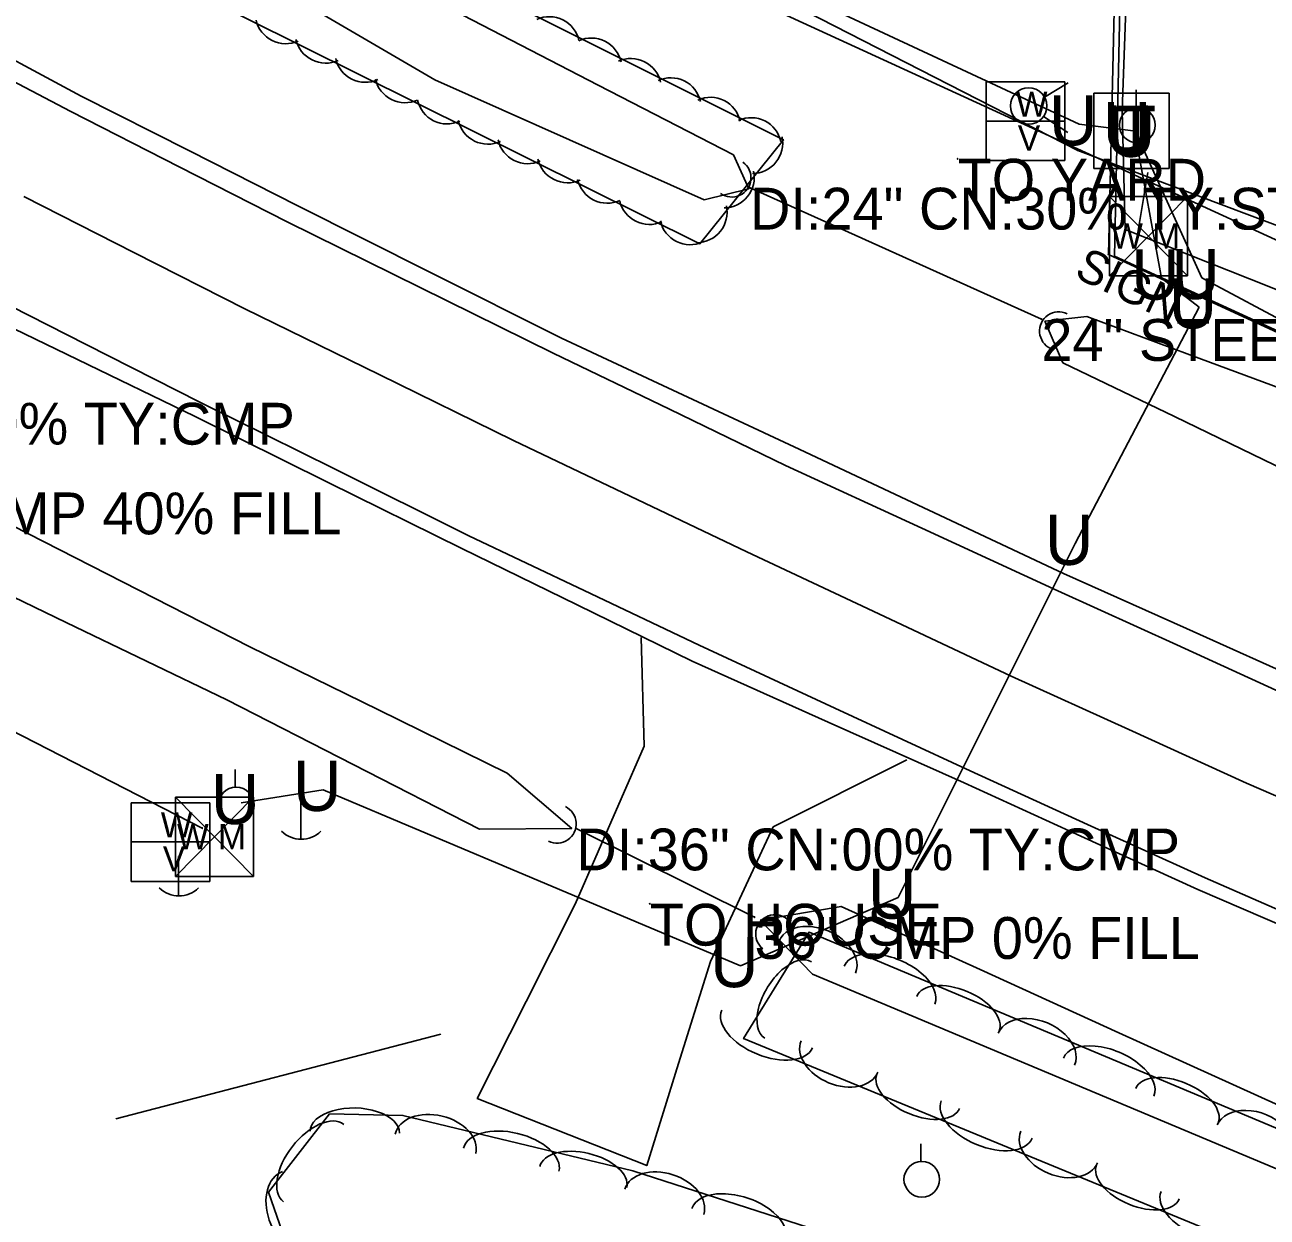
# Model space of a CAD drawing. Extents: x 1441650 to 1491889, y 345904 to 358319.
# Drawn here: x 1445494.4 to 1445643, y 354585.4 to 354728 of the extents above; entities that cross this region are included whole.
import ezdxf

# ---------------------------------------------------------------- set-up
doc = ezdxf.new("R2010")
doc.units = 0
for name, color, linetype in [('Default', 7, 'Continuous'), ('S_CROSS_DRAIN', 7, 'Continuous'), ('S_CROSS_DRAIN_ANNOT', 7, 'Continuous'), ('S_DITCHLINE', 7, 'Continuous'), ('S_DRG_PT_SYM', 7, 'Continuous'), ('S_EDGE_PAVEMENT', 7, 'Continuous'), ('S_FENCE', 7, 'Continuous'), ('S_GAS_UTILITIES', 7, 'Continuous'), ('S_GRAVEL_ROAD', 7, 'Continuous'), ('S_MSC_PT_SYM', 7, 'Continuous'), ('S_PAVEMENT_CROWN', 7, 'Continuous'), ('S_SHOULDER', 7, 'Continuous'), ('S_SIGN_ANNOT', 7, 'Continuous'), ('S_SURVEY_TEXT_ANNOT', 7, 'Continuous'), ('S_TELEPHONE_UTILITIES', 7, 'Continuous'), ('S_TRAILS', 7, 'Continuous'), ('S_TREE', 7, 'Continuous'), ('S_UNDERGROUND_CABLE', 7, 'Continuous'), ('S_UTILITY_POLE', 7, 'Continuous'), ('S_UTL_PT_SYM', 7, 'Continuous'), ('S_WATER_UTILITIES', 7, 'Continuous')]:
    doc.layers.add(name, color=color, linetype=linetype)

msp = doc.modelspace()

# ---------------------------------------------------------------- linework, layer by layer
at = {"layer": 'S_CROSS_DRAIN'}
for p, q in [((1445581.12, 354708.5), (1445615.98, 354692.8)), ((1445560.34, 354631.87), (1445581.67, 354621.28))]:
    msp.add_line(p, q, dxfattribs=at)
for centre, start, end in [((1445578.94, 354709.69), 234.4858, 54.815), ((1445618.06, 354691.36), 64.431, 244.7602), ((1445558.03, 354632.42), 243.9904, 64.3196), ((1445584.1, 354619.27), 50.7104, 231.0396)]:
    msp.add_arc(centre, 2.3, start, end, dxfattribs=at)
at = {"layer": 'S_DITCHLINE'}
for points in [[(1445507.34, 354745.43), (1445514.42, 354744.42), (1445530.6, 354736.77), (1445546.78, 354729.13), (1445562.96, 354720.78), (1445579.14, 354712.42), (1445580.96, 354708.37), (1445575.63, 354707.06), (1445559.53, 354714.22), (1445543.42, 354721.39), (1445526.18, 354731.48), (1445508.94, 354741.57)], [(1445616.39, 354692.54), (1445618.56, 354687.58), (1445631.89, 354681.14), (1445645.22, 354674.69), (1445661.2, 354667.77), (1445677.18, 354660.84), (1445681.37, 354663.16), (1445677.91, 354667.65), (1445663.36, 354675.29), (1445648.8, 354682.93), (1445635.12, 354688.02), (1445621.43, 354693.11)], [(1445475.5, 354671.85), (1445483.37, 354672.92), (1445502.31, 354663.27), (1445521.26, 354653.62), (1445536.66, 354646.05), (1445552.07, 354638.49), (1445559.8, 354631.89), (1445548.74, 354631.79), (1445533.63, 354639.52), (1445518.52, 354647.25), (1445499.3, 354656.52), (1445480.07, 354665.8)]]:
    msp.add_lwpolyline(points, close=True, dxfattribs=at)
for points in [[(1445582.34, 354620.9), (1445592.01, 354622.56), (1445608.64, 354615.01), (1445625.26, 354607.46), (1445641.89, 354599.91), (1445658.52, 354592.36), (1445679.06, 354584.26), (1445699.61, 354576.16), (1445720.15, 354568.06), (1445740.7, 354559.96), (1445763.19, 354552.12), (1445785.68, 354544.28)], [(1445582.34, 354620.91), (1445588.59, 354614.45), (1445606.17, 354607.08), (1445623.76, 354599.71), (1445641.34, 354592.33), (1445658.93, 354584.96), (1445678.55, 354576.91), (1445698.18, 354568.86), (1445717.81, 354560.81), (1445737.43, 354552.76), (1445759.94, 354544.74), (1445782.44, 354536.73)]]:
    msp.add_lwpolyline(points, dxfattribs=at)
at = {"layer": 'S_DRG_PT_SYM'}
for points in [[(1445581.12, 354708.5), (1445581.12, 354708.55), (1445581.12, 354708.5), (1445581.07, 354708.5), (1445581.12, 354708.5), (1445581.12, 354708.45), (1445581.12, 354708.5), (1445581.17, 354708.5)], [(1445615.98, 354692.8), (1445615.98, 354692.85), (1445615.98, 354692.8), (1445615.93, 354692.8), (1445615.98, 354692.8), (1445615.98, 354692.75), (1445615.98, 354692.8), (1445616.03, 354692.8)], [(1445560.34, 354631.87), (1445560.34, 354631.92), (1445560.34, 354631.87), (1445560.29, 354631.87), (1445560.34, 354631.87), (1445560.34, 354631.82), (1445560.34, 354631.87), (1445560.39, 354631.87)], [(1445581.67, 354621.28), (1445581.67, 354621.33), (1445581.67, 354621.28), (1445581.62, 354621.28), (1445581.67, 354621.28), (1445581.67, 354621.23), (1445581.67, 354621.28), (1445581.72, 354621.28)]]:
    msp.add_lwpolyline(points, dxfattribs=at)
at = {"layer": 'S_EDGE_PAVEMENT'}
for points in [[(1445484.93, 354725.42), (1445499.88, 354717.6), (1445512.81, 354711.01), (1445525.74, 354704.41), (1445541.65, 354696.57), (1445557.56, 354688.73), (1445571.47, 354682.02), (1445585.38, 354675.3), (1445601.66, 354667.81), (1445617.95, 354660.31), (1445632.18, 354653.82), (1445646.4, 354647.34), (1445662.43, 354640.42), (1445678.45, 354633.5), (1445695.75, 354626.25), (1445713.05, 354619.01), (1445724.98, 354614.31), (1445736.91, 354609.62), (1445758.93, 354600.82), (1445773.25, 354595.45)], [(1445488.09, 354696.66), (1445501.69, 354689.76), (1445515.29, 354682.87), (1445531.39, 354674.88), (1445547.49, 354666.89), (1445561.27, 354660.34), (1445575.05, 354653.79), (1445591.25, 354646.28), (1445607.45, 354638.77), (1445621.51, 354632.37), (1445635.57, 354625.97), (1445651.53, 354619.01), (1445667.49, 354612.05), (1445685.63, 354604.56), (1445703.76, 354597.07), (1445715.54, 354592.42), (1445727.31, 354587.77), (1445749.22, 354579.28)]]:
    msp.add_lwpolyline(points, dxfattribs=at)
at = {"layer": 'S_FENCE'}
for p, q in [((1445625.45, 354762.08), (1445624, 354700.53)), ((1445624, 354700.53), (1445689.04, 354670.46))]:
    msp.add_line(p, q, dxfattribs=at)
msp.add_lwpolyline([(1445689.01, 354670.85), (1445624.73, 354700.32), (1445629.67, 354929.96)], dxfattribs=at)
at = {"layer": 'S_GAS_UTILITIES'}
msp.add_line((1445467.8, 354783.19), (1445792.48, 354634.07), dxfattribs=at)
at = {"layer": 'S_GRAVEL_ROAD'}
for points in [[(1445627.26, 354762.2), (1445626.45, 354739.95), (1445625.64, 354717.69), (1445626.02, 354703.49), (1445640.88, 354697.59), (1445655.73, 354691.69), (1445674.52, 354683.52), (1445693.31, 354675.35)], [(1445568.09, 354654.72), (1445568.47, 354641.73), (1445560.19, 354622.82), (1445554.34, 354611.2), (1445548.49, 354599.59), (1445568.77, 354591.56), (1445572.57, 354603.77), (1445576.38, 354615.98), (1445583.91, 354632.06), (1445599.9, 354640.07)]]:
    msp.add_lwpolyline(points, dxfattribs=at)
at = {"layer": 'S_MSC_PT_SYM'}
for points in [[(1445605.96, 354711.96), (1445605.96, 354712.01), (1445605.96, 354711.96), (1445605.91, 354711.96), (1445605.96, 354711.96), (1445605.96, 354711.91), (1445605.96, 354711.96), (1445606.01, 354711.96)], [(1445624, 354700.53), (1445624, 354700.58), (1445624, 354700.53), (1445623.95, 354700.53), (1445624, 354700.53), (1445624, 354700.48), (1445624, 354700.53), (1445624.05, 354700.53)], [(1445569.14, 354622.87), (1445569.14, 354622.92), (1445569.14, 354622.87), (1445569.09, 354622.87), (1445569.14, 354622.87), (1445569.14, 354622.82), (1445569.14, 354622.87), (1445569.19, 354622.87)]]:
    msp.add_lwpolyline(points, dxfattribs=at)
at = {"layer": 'S_PAVEMENT_CROWN'}
msp.add_lwpolyline([(1445494.25, 354707.44), (1445507.47, 354700.72), (1445520.69, 354694.01), (1445536.76, 354686.15), (1445552.82, 354678.29), (1445566.78, 354671.62), (1445580.74, 354664.95), (1445596.54, 354657.53), (1445612.35, 354650.11), (1445626.43, 354643.71), (1445640.51, 354637.3), (1445656.41, 354630.43), (1445672.31, 354623.56), (1445690.37, 354616.08), (1445708.44, 354608.6), (1445720.29, 354603.76), (1445732.14, 354598.92), (1445754.09, 354590.41), (1445768.79, 354584.89)], dxfattribs=at)
at = {"layer": 'S_SHOULDER'}
for points in [[(1445486.09, 354727.49), (1445501.1, 354719.47), (1445514.07, 354712.91), (1445527.04, 354706.35), (1445542.81, 354698.42), (1445558.58, 354690.5), (1445572.49, 354684), (1445586.4, 354677.5), (1445602.52, 354669.94), (1445618.64, 354662.39), (1445633.34, 354655.78), (1445648.04, 354649.17), (1445663.52, 354642.27), (1445679, 354635.36), (1445696.46, 354628.23), (1445713.93, 354621.11), (1445725.54, 354616.41), (1445737.15, 354611.72), (1445759.69, 354603.15), (1445774.03, 354597.98)], [(1445486.7, 354694.71), (1445500.67, 354687.95), (1445514.65, 354681.18), (1445530.65, 354673.27), (1445546.65, 354665.35), (1445560.43, 354658.62), (1445574.21, 354651.88), (1445590.47, 354644.61), (1445606.73, 354637.35), (1445620.72, 354630.96), (1445634.71, 354624.57), (1445650.81, 354617.66), (1445666.9, 354610.74), (1445684.95, 354603.11), (1445703.01, 354595.47), (1445714.81, 354590.83), (1445726.62, 354586.19), (1445748.54, 354577.61)]]:
    msp.add_lwpolyline(points, dxfattribs=at)
at = {"layer": 'S_SIGN_ANNOT'}
msp.add_line((1445628.73, 354710.31), (1445627.28, 354701.71), dxfattribs=at)
at = {"layer": 'S_TELEPHONE_UTILITIES'}
msp.add_lwpolyline([(1445622.26, 354710.81), (1445622.26, 354719.81), (1445631.26, 354719.81), (1445631.26, 354710.81)], close=True, dxfattribs=at)
at = {"layer": 'S_TRAILS'}
msp.add_lwpolyline([(1445544.12, 354607.3), (1445505.23, 354597.15)], dxfattribs=at)
at = {"layer": 'S_TREE'}
for points in [[(1445512.49, 354750.57), (1445585.12, 354714.24), (1445575.13, 354701.81), (1445500.4, 354738.94), (1445509.57, 354750.24), (1445513.86, 354750.79)], [(1445526.2, 354580.7), (1445523.5, 354588.38), (1445530.81, 354597.74), (1445539.6, 354597.56), (1445567.12, 354590.95), (1445590.71, 354583.33), (1445596.17, 354567.66), (1445606.51, 354557.63), (1445625.61, 354574.56), (1445637.75, 354583.11), (1445580.36, 354606.75), (1445588.18, 354619.49), (1445674.98, 354583.08), (1445753.74, 354549.77), (1445823.46, 354524.76), (1445921.74, 354488.99), (1446061.75, 354449.1)]]:
    msp.add_lwpolyline(points, dxfattribs=at)
for centre, start, end in [((1445525.57, 354729.36), 192.7796, 294.3765), ((1445530.34, 354727.04), 192.7796, 294.3765), ((1445535.1, 354724.75), 192.7796, 294.3765), ((1445539.85, 354722.31), 192.7796, 294.3765), ((1445544.89, 354719.77), 192.7796, 294.3765), ((1445549.76, 354717.35), 192.7796, 294.3765), ((1445554.53, 354715.02), 192.7796, 294.3765), ((1445581.39, 354713.84), 270.4003, 11.9972), ((1445559.29, 354712.73), 192.7796, 294.3765), ((1445577.99, 354709.73), 270.4003, 11.9972), ((1445564.04, 354710.29), 192.7796, 294.3765), ((1445569.08, 354707.75), 192.7796, 294.3765), ((1445574.74, 354705.57), 270.4003, 11.9972), ((1445573.95, 354705.33), 192.7796, 294.3765)]:
    msp.add_arc(centre, 3.64, start, end, dxfattribs=at)
for centre, major_axis, ratio, start_param, end_param in [((1445557.1, 354725.31), (-1.63, -3.26), 0.999999, 2.254992, 4.028193), ((1445562.13, 354722.76), (-1.63, -3.26), 0.999999, 2.254993, 4.028194), ((1445566.87, 354720.31), (-1.63, -3.26), 0.999999, 2.254993, 4.028194), ((1445571.63, 354718.01), (-1.63, -3.26), 0.999999, 2.254993, 4.028194), ((1445576.39, 354715.67), (-1.63, -3.26), 0.999999, 2.254992, 4.028193), ((1445581.25, 354713.23), (-1.63, -3.26), 0.999999, 2.254992, 4.028193), ((1445589.17, 354616.49), (-4.57, 1.92), 0.685297, 3.141663, 6.283256), ((1445585.68, 354611.37), (-2.8, -4.56), 0.540812, 3.141602, 6.283195), ((1445597.81, 354613.15), (-5.41, 2.27), 0.550068, 3.141636, 6.283229), ((1445605.99, 354609.72), (-4.93, 2.07), 0.540688, 3.141635, 6.283227), ((1445583.16, 354607.9), (5.43, -2.24), 0.550058, 3.141593, 6.283185), ((1445615.39, 354605.49), (-4.57, 1.92), 0.685297, 3.141663, 6.283256), ((1445591.82, 354604.61), (4.58, -1.89), 0.685284, 3.141593, 6.283185), ((1445624.03, 354602.15), (-5.41, 2.27), 0.550068, 3.141636, 6.283229), ((1445601.25, 354600.45), (4.94, -2.04), 0.540678, 3.141593, 6.283185), ((1445632.2, 354598.72), (-4.93, 2.07), 0.540688, 3.141635, 6.283227), ((1445609.44, 354597.07), (5.43, -2.24), 0.550058, 3.141593, 6.283185), ((1445528.91, 354591.86), (-3.61, -4.63), 0.550079, 3.141593, 6.283185), ((1445533.83, 354595.56), (-5.35, 0.11), 0.540687, 3.141619, 6.283212), ((1445543.49, 354594.18), (-4.82, 1.16), 0.685285, 3.141593, 6.283185), ((1445641.6, 354594.5), (-4.57, 1.92), 0.685297, 3.141663, 6.283256), ((1445552.55, 354592.27), (-5.71, 1.37), 0.550059, 3.141593, 6.283185), ((1445618.1, 354593.78), (4.58, -1.89), 0.685284, 3.141593, 6.283185), ((1445561.17, 354590.2), (-5.2, 1.25), 0.540679, 3.141593, 6.283185), ((1445627.53, 354589.62), (4.94, -2.04), 0.540678, 3.141593, 6.283185), ((1445526.81, 354586.16), (1.64, -4.68), 0.685296, 3.141593, 6.283185), ((1445570.86, 354587.24), (-4.72, 1.52), 0.685285, 3.141614, 6.283206), ((1445579.75, 354584.64), (-5.58, 1.8), 0.550059, 3.141605, 6.283198), ((1445635.73, 354586.24), (5.43, -2.24), 0.550058, 3.141593, 6.283185)]:
    msp.add_ellipse(centre, major_axis=major_axis, ratio=ratio, start_param=start_param, end_param=end_param, dxfattribs=at)
at = {"layer": 'S_UNDERGROUND_CABLE'}
for p, q in [((1445499.56, 354772.4), (1445620.52, 354716.12)), ((1445620.52, 354716.12), (1445626.95, 354715.29)), ((1445626.95, 354715.29), (1445627.45, 354714.74)), ((1445627.21, 354714.89), (1445630.35, 354697.67)), ((1445627.45, 354714.74), (1445635.16, 354697.74)), ((1445630.35, 354697.67), (1445634.84, 354694.22)), ((1445635.16, 354697.74), (1445715.14, 354654.84)), ((1445634.84, 354694.22), (1445620.04, 354665.95)), ((1445620.04, 354665.95), (1445598.86, 354623.64)), ((1445530.07, 354636.51), (1445520.25, 354634.94)), ((1445579.98, 354615.45), (1445530.07, 354636.51)), ((1445598.86, 354623.64), (1445579.98, 354615.45))]:
    msp.add_line(p, q, dxfattribs=at)
at = {"layer": 'S_UTILITY_POLE'}
for p, q in [((1445627.34, 354718.12), (1445627.34, 354720.23)), ((1445519.53, 354636.83), (1445519.53, 354638.94)), ((1445527.37, 354635.32), (1445527.37, 354630.59)), ((1445512.74, 354628.53), (1445512.74, 354623.81)), ((1445601.55, 354592.06), (1445601.55, 354594.17))]:
    msp.add_line(p, q, dxfattribs=at)
for centre in [(1445627.46, 354715.98), (1445519.65, 354634.69), (1445601.67, 354589.92)]:
    msp.add_circle(centre, 2.13, dxfattribs=at)
for centre in [(1445527.43, 354634.01), (1445512.8, 354627.23)]:
    msp.add_arc(centre, 3.41, 226.3972, 313.6028, dxfattribs=at)
at = {"layer": 'S_UTL_PT_SYM'}
for points in [[(1445620.33, 354712.97), (1445620.33, 354713.02), (1445620.33, 354712.97), (1445620.28, 354712.97), (1445620.33, 354712.97), (1445620.33, 354712.92), (1445620.33, 354712.97), (1445620.38, 354712.97)], [(1445515.59, 354631.91), (1445515.59, 354631.96), (1445515.59, 354631.91), (1445515.54, 354631.91), (1445515.59, 354631.91), (1445515.59, 354631.86), (1445515.59, 354631.91), (1445515.64, 354631.91)]]:
    msp.add_lwpolyline(points, dxfattribs=at)
at = {"layer": 'S_WATER_UTILITIES'}
for p, q in [((1445447.71, 354801.29), (1445620.33, 354712.97)), ((1445328.49, 354727.82), (1445515.59, 354631.91)), ((1445609.37, 354721.17), (1445618.79, 354721.17)), ((1445609.37, 354711.75), (1445609.37, 354721.17)), ((1445616.36, 354719.33), (1445619.18, 354721.06)), ((1445618.79, 354721.17), (1445618.79, 354711.75)), ((1445609.37, 354716.48), (1445618.79, 354716.48)), ((1445616.23, 354717.02), (1445619.14, 354715.09)), ((1445620.33, 354712.97), (1445810, 354641.4)), ((1445618.79, 354711.75), (1445609.37, 354711.75)), ((1445624.14, 354707.47), (1445633.48, 354707.47)), ((1445624.14, 354707.47), (1445624.14, 354697.97)), ((1445624.14, 354707.47), (1445633.48, 354697.97)), ((1445633.48, 354707.47), (1445624.14, 354697.97)), ((1445633.48, 354707.47), (1445633.48, 354697.97)), ((1445624.14, 354697.97), (1445633.48, 354697.97)), ((1445507.08, 354634.96), (1445516.49, 354634.96)), ((1445507.08, 354625.55), (1445507.08, 354634.96)), ((1445512.37, 354635.63), (1445521.7, 354635.63)), ((1445512.37, 354635.63), (1445512.37, 354626.14)), ((1445512.37, 354635.63), (1445521.7, 354626.14)), ((1445521.7, 354635.63), (1445512.37, 354626.14)), ((1445516.49, 354634.96), (1445516.49, 354625.55)), ((1445521.7, 354635.63), (1445521.7, 354626.14)), ((1445507.08, 354630.27), (1445516.49, 354630.27)), ((1445512.37, 354626.14), (1445521.7, 354626.14)), ((1445516.49, 354625.55), (1445507.08, 354625.55))]:
    msp.add_line(p, q, dxfattribs=at)
msp.add_circle((1445614.45, 354718.28), 2.18, dxfattribs=at)

# ---------------------------------------------------------------- texts
at = {"layer": 'Default'}
for p in [(1445616.89, 354713.57), (1445623.32, 354712.75), (1445623.58, 354712.34), (1445623.83, 354712.19), (1445626.72, 354695.12), (1445631.53, 354695.19), (1445631.21, 354691.68), (1445616.41, 354663.4), (1445526.44, 354633.97), (1445516.62, 354632.4), (1445595.23, 354621.09), (1445576.35, 354612.9)]:
    msp.add_text('U', height=6, rotation=360, dxfattribs=at).set_placement(p)
at = {"layer": 'S_CROSS_DRAIN_ANNOT'}
for s, p in [('DI:24" CN:30% TY:STEEL', (1445581.12, 354703.5)), ('24" STEEL PIPE 30% FILL', (1445615.98, 354687.8)), ('DI:24" CN:40% TY:CMP', (1445454.44, 354677.78)), ('24" CMP 40% FILL', (1445475.26, 354667.06)), ('DI:36" CN:00% TY:CMP', (1445560.34, 354626.87)), ('36" CMP 0% FILL', (1445581.67, 354616.28))]:
    msp.add_text(s, height=5, dxfattribs=at).set_placement(p)
at = {"layer": 'S_SIGN_ANNOT'}
msp.add_text('SIGN', height=4, rotation=334.5511, dxfattribs=at).set_placement((1445619.77, 354697.88))
at = {"layer": 'S_SURVEY_TEXT_ANNOT'}
for s, p in [('TO YARD', (1445605.96, 354706.96)), ('TO HOUSE', (1445569.14, 354617.87))]:
    msp.add_text(s, height=5, dxfattribs=at).set_placement(p)
at = {"layer": 'S_TELEPHONE_UTILITIES'}
msp.add_text('T', height=6, rotation=360, dxfattribs=at).set_placement((1445624.82, 354712.31))
at = {"layer": 'S_WATER_UTILITIES'}
for s, p in [('W', (1445612.93, 354717.01)), ('V', (1445613.16, 354712.95)), ('W M', (1445624.34, 354701.23)), ('W', (1445510.63, 354630.8)), ('W M', (1445512.57, 354629.4)), ('V', (1445510.87, 354626.74))]:
    msp.add_text(s, height=3, rotation=360, dxfattribs=at).set_placement(p)

doc.saveas('drawing.dxf')
